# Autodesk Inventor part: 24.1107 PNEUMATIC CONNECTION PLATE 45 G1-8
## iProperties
Created: 2007-01
Part Number: 24.1107 PNEUMATIC CONNECTION PLATE 45 G1-8
Document SubType Name: Modeling
Designer: Andy Moles
Material: Aluminum-6061
Mass: 152.078 g
Surface Area: 129.468 cm^2
Volume: 56.1174 cm^3
Density: 2.71 g/cm^3
Author: Andy Moles
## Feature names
1. Extrusion1
2. Hole1
3. Hole2
4. Fillet1
5. Revolution1
6. Extrusion2
7. Chamfer1
